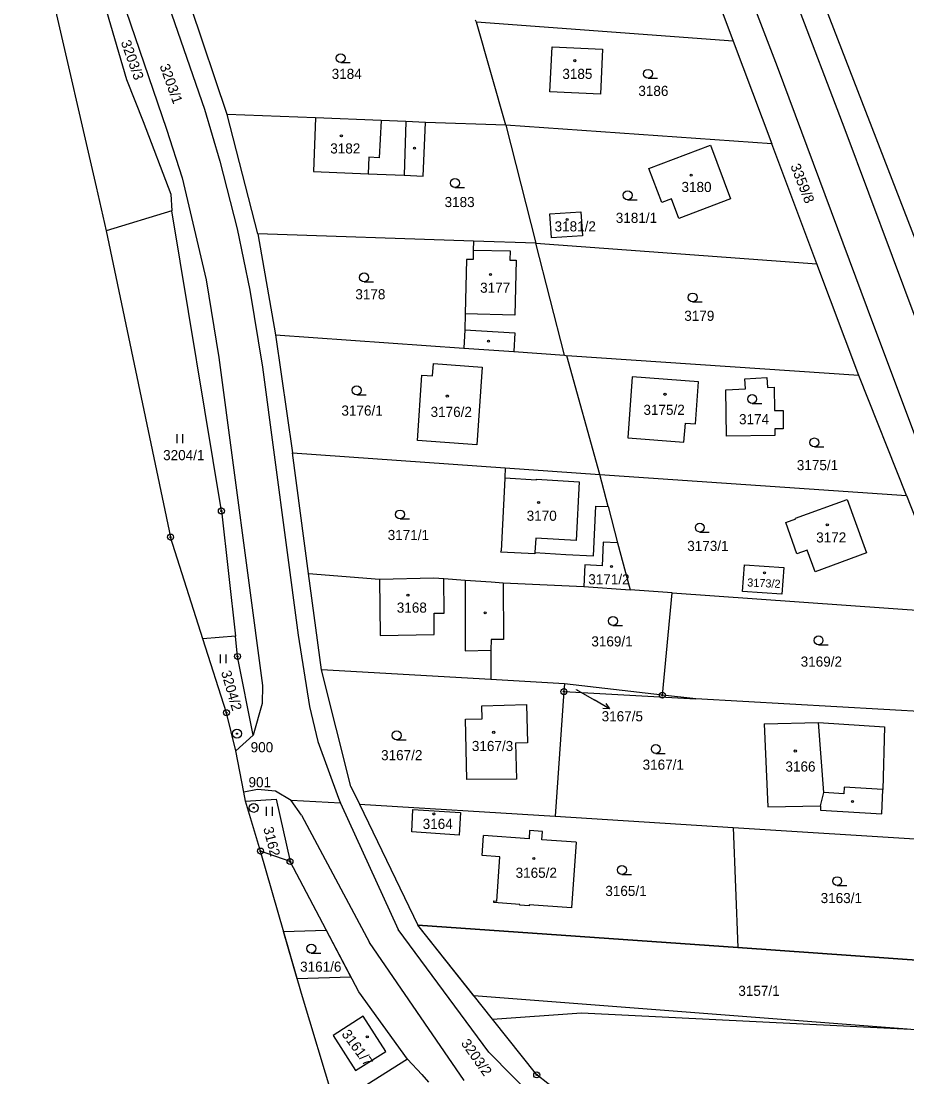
# Model space of a CAD drawing. Extents: x -755819 to -753140, y -1169796 to -1166000.
# Drawn here: x -754247.6 to -754098.6, y -1169675.5 to -1169498 of the extents above; entities that cross this region are included whole.
import ezdxf

# ---------------------------------------------------------------- set-up
doc = ezdxf.new("R2010")
doc.units = 0
for name, color, linetype in [('Vrstva 1', 7, 'Continuous'), ('Vrstva 13', 7, 'Continuous'), ('Vrstva 16', 7, 'Continuous'), ('Vrstva 17', 7, 'Continuous'), ('Vrstva 18', 7, 'Continuous'), ('Vrstva 19', 7, 'Continuous'), ('Vrstva 24', 7, 'Continuous'), ('Vrstva 25', 7, 'Continuous'), ('Vrstva 27', 7, 'Continuous'), ('Vrstva 4', 7, 'Continuous'), ('Vrstva 6', 7, 'Continuous')]:
    doc.layers.add(name, color=color, linetype=linetype)

msp = doc.modelspace()

# ---------------------------------------------------------------- linework, layer by layer
at = {"layer": 'Vrstva 1'}
for p, q in [((-754124.54, -1169463.98), (-754097.09, -1169534.95)), ((-754120.39, -1169505.66), (-754134.47, -1169468.92)), ((-754134.3, -1169483.93), (-754127.84, -1169501.33)), ((-754232.95, -1169487.36), (-754223.15, -1169516.12)), ((-754225.64, -1169486.93), (-754216.78, -1169512.79)), ((-754235.36, -1169489.1), (-754229.85, -1169507.79)), ((-754212.93, -1169513.65), (-754219.05, -1169495.48)), ((-754171, -1169498.11), (-754171.18, -1169497.81)), ((-754127.84, -1169501.33), (-754171, -1169498.11)), ((-754166.07, -1169515.47), (-754171, -1169498.11)), ((-754158.67, -1169509.85), (-754158.28, -1169502.3)), ((-754158.28, -1169502.3), (-754149.8, -1169502.7)), ((-754149.8, -1169502.7), (-754150.13, -1169510.23)), ((-754127.84, -1169501.33), (-754121.34, -1169518.58)), ((-754105.23, -1169546.26), (-754120.39, -1169505.66)), ((-754229.85, -1169507.79), (-754227.05, -1169514.85)), ((-754150.13, -1169510.23), (-754158.67, -1169509.85)), ((-754216.78, -1169512.79), (-754214.15, -1169521.5)), ((-754227.05, -1169514.85), (-754222.4, -1169527.04)), ((-754198.07, -1169514.21), (-754212.93, -1169513.65)), ((-754207.77, -1169533.74), (-754212.93, -1169513.65)), ((-754198.07, -1169514.21), (-754198.44, -1169523.24)), ((-754187.05, -1169514.68), (-754198.07, -1169514.21)), ((-754182.9, -1169514.85), (-754187.05, -1169514.68)), ((-754179.58, -1169514.99), (-754182.9, -1169514.85)), ((-754179.95, -1169524.02), (-754179.58, -1169514.99)), ((-754166.07, -1169515.47), (-754179.58, -1169514.99)), ((-754223.15, -1169516.12), (-754220.49, -1169524.34)), ((-754121.34, -1169518.58), (-754166.07, -1169515.47)), ((-754166.07, -1169515.47), (-754161.04, -1169535.31)), ((-754142.01, -1169522.75), (-754131.63, -1169518.81)), ((-754131.63, -1169518.81), (-754128.27, -1169527.84)), ((-754113.75, -1169538.75), (-754121.34, -1169518.58)), ((-754214.15, -1169521.5), (-754211.27, -1169532.88)), ((-754198.44, -1169523.24), (-754189.25, -1169523.64)), ((-754189.25, -1169523.64), (-754183.17, -1169523.88)), ((-754183.17, -1169523.88), (-754179.95, -1169524.02)), ((-754139.84, -1169528.48), (-754142.01, -1169522.75)), ((-754220.49, -1169524.34), (-754216.47, -1169541.49)), ((-754222.4, -1169527.04), (-754222.27, -1169529.89)), ((-754138.21, -1169527.87), (-754139.84, -1169528.48)), ((-754136.97, -1169531.14), (-754138.21, -1169527.87)), ((-754128.27, -1169527.84), (-754136.97, -1169531.14)), ((-754222.27, -1169529.89), (-754233.29, -1169533.21)), ((-754213.91, -1169580.33), (-754222.27, -1169529.89)), ((-754158.68, -1169530.39), (-754153.45, -1169530.02)), ((-754158.38, -1169534.43), (-754158.68, -1169530.39)), ((-754153.45, -1169530.02), (-754153.15, -1169534.08)), ((-754211.27, -1169532.88), (-754209.11, -1169543.21)), ((-754171.52, -1169534.96), (-754207.77, -1169533.74)), ((-754207.77, -1169533.74), (-754204.81, -1169550.71)), ((-754153.15, -1169534.08), (-754158.38, -1169534.43)), ((-754171.55, -1169536.46), (-754171.58, -1169538.05)), ((-754171.52, -1169534.96), (-754171.55, -1169536.46)), ((-754161.04, -1169535.31), (-754171.52, -1169534.96)), ((-754156.18, -1169554.11), (-754161.04, -1169535.31)), ((-754161.04, -1169535.31), (-754113.75, -1169538.75)), ((-754172.68, -1169538.03), (-754172.92, -1169547.18)), ((-754171.58, -1169538.05), (-754172.68, -1169538.03)), ((-754106.67, -1169557.57), (-754113.75, -1169538.75)), ((-754216.47, -1169541.49), (-754214.32, -1169554.53)), ((-754209.11, -1169543.21), (-754206.99, -1169556.16)), ((-754172.92, -1169547.18), (-754172.97, -1169549.88)), ((-754090.22, -1169586.43), (-754105.23, -1169546.26)), ((-754204.81, -1169550.71), (-754173.12, -1169552.98)), ((-754204.81, -1169550.71), (-754201.96, -1169570.53)), ((-754172.97, -1169549.88), (-754173.12, -1169552.98)), ((-754173.12, -1169552.98), (-754164.74, -1169553.49)), ((-754164.74, -1169553.49), (-754156.18, -1169554.11)), ((-754156.18, -1169554.11), (-754155.78, -1169554.22)), ((-754150.26, -1169574.2), (-754155.78, -1169554.22)), ((-754106.67, -1169557.57), (-754155.78, -1169554.22)), ((-754214.32, -1169554.53), (-754206.99, -1169609.66)), ((-754178.39, -1169557.63), (-754178.24, -1169555.53)), ((-754178.24, -1169555.53), (-754170.05, -1169556.15)), ((-754170.05, -1169556.15), (-754170.96, -1169569.19)), ((-754206.99, -1169556.16), (-754200.97, -1169601.19)), ((-754180.94, -1169568.49), (-754180.18, -1169557.5)), ((-754180.18, -1169557.5), (-754178.39, -1169557.63)), ((-754144.82, -1169557.79), (-754145.57, -1169568.06)), ((-754133.67, -1169558.6), (-754144.82, -1169557.79)), ((-754125.86, -1169558.1), (-754122.15, -1169557.87)), ((-754122.15, -1169557.87), (-754122.05, -1169559.59)), ((-754098.65, -1169577.71), (-754106.67, -1169557.57)), ((-754134.16, -1169565.68), (-754133.67, -1169558.6)), ((-754125.76, -1169559.82), (-754125.86, -1169558.1)), ((-754122.05, -1169559.59), (-754120.91, -1169559.54)), ((-754120.91, -1169559.54), (-754120.87, -1169563.43)), ((-754129.06, -1169559.94), (-754125.76, -1169559.82)), ((-754128.94, -1169567.73), (-754129.06, -1169559.94)), ((-754120.87, -1169563.43), (-754119.42, -1169563.42)), ((-754119.42, -1169563.42), (-754119.4, -1169566.53)), ((-754136.11, -1169568.75), (-754135.86, -1169565.59)), ((-754135.86, -1169565.59), (-754134.16, -1169565.68)), ((-754119.4, -1169566.53), (-754120.84, -1169566.54)), ((-754120.84, -1169566.54), (-754120.83, -1169567.65)), ((-754170.96, -1169569.19), (-754180.94, -1169568.49)), ((-754145.57, -1169568.06), (-754136.11, -1169568.75)), ((-754120.83, -1169567.65), (-754128.94, -1169567.73)), ((-754201.96, -1169570.53), (-754166.15, -1169573.07)), ((-754199.27, -1169590.84), (-754201.96, -1169570.53)), ((-754166.15, -1169573.07), (-754166.23, -1169574.76)), ((-754166.15, -1169573.07), (-754150.26, -1169574.2)), ((-754166.24, -1169574.87), (-754166.87, -1169587.05)), ((-754166.23, -1169574.76), (-754166.24, -1169574.87)), ((-754148.88, -1169579.57), (-754150.26, -1169574.2)), ((-754150.26, -1169574.2), (-754098.65, -1169577.71)), ((-754117.33, -1169581.52), (-754108.65, -1169578.39)), ((-754108.65, -1169578.39), (-754105.85, -1169586.16)), ((-754098.65, -1169577.71), (-754090.97, -1169597.45)), ((-754213.91, -1169580.33), (-754211.56, -1169601.41)), ((-754151.32, -1169587.88), (-754150.93, -1169579.51)), ((-754150.93, -1169579.51), (-754148.88, -1169579.57)), ((-754148.88, -1169579.57), (-754147.3, -1169585.69)), ((-754118.98, -1169582.28), (-754117.28, -1169581.66)), ((-754117.12, -1169587.54), (-754118.98, -1169582.28)), ((-754117.28, -1169581.66), (-754117.33, -1169581.52)), ((-754149.7, -1169585.59), (-754149.86, -1169589.53)), ((-754147.3, -1169585.69), (-754149.7, -1169585.59)), ((-754147.3, -1169585.69), (-754145.18, -1169593.58)), ((-754105.85, -1169586.16), (-754105.41, -1169587.38)), ((-754166.88, -1169587.24), (-754166.87, -1169587.05)), ((-754161.19, -1169587.53), (-754166.88, -1169587.24)), ((-754161.18, -1169587.34), (-754161.19, -1169587.53)), ((-754161.18, -1169587.34), (-754155.98, -1169587.63)), ((-754155.98, -1169587.63), (-754151.32, -1169587.88)), ((-754115.38, -1169586.91), (-754117.12, -1169587.54)), ((-754114.06, -1169590.58), (-754115.38, -1169586.91)), ((-754105.41, -1169587.38), (-754114.06, -1169590.58)), ((-754152.8, -1169589.41), (-754152.94, -1169593.01)), ((-754149.86, -1169589.53), (-754152.8, -1169589.41)), ((-754126.24, -1169593.87), (-754125.92, -1169589.4)), ((-754125.92, -1169589.4), (-754119.32, -1169589.81)), ((-754119.32, -1169589.81), (-754119.64, -1169594.33)), ((-754199.27, -1169590.84), (-754187.29, -1169591.8)), ((-754197.05, -1169607.04), (-754199.27, -1169590.84)), ((-754187.29, -1169591.8), (-754178.18, -1169591.58)), ((-754178.18, -1169591.58), (-754176.48, -1169591.7)), ((-754176.48, -1169591.7), (-754172.91, -1169591.96)), ((-754172.91, -1169591.96), (-754168.55, -1169592.26)), ((-754168.55, -1169592.26), (-754166.54, -1169592.41)), ((-754166.54, -1169592.41), (-754152.94, -1169593.01)), ((-754166.54, -1169592.41), (-754166.44, -1169601.94)), ((-754152.94, -1169593.01), (-754145.18, -1169593.58)), ((-754138.1, -1169594.09), (-754145.18, -1169593.58)), ((-754139.73, -1169611.3), (-754138.1, -1169594.09)), ((-754138.1, -1169594.09), (-754090.97, -1169597.45)), ((-754119.64, -1169594.33), (-754126.24, -1169593.87)), ((-754211.19, -1169604.79), (-754211.56, -1169601.41)), ((-754200.97, -1169601.19), (-754199.08, -1169613.21)), ((-754168.54, -1169601.94), (-754168.57, -1169603.73)), ((-754166.44, -1169601.94), (-754168.54, -1169601.94)), ((-754168.57, -1169603.73), (-754168.58, -1169608.67)), ((-754208.58, -1169618.01), (-754211.19, -1169604.79)), ((-754168.58, -1169608.67), (-754197.05, -1169607.04)), ((-754192.11, -1169626.67), (-754197.05, -1169607.04)), ((-754156.21, -1169609.38), (-754168.58, -1169608.67)), ((-754156.21, -1169609.38), (-754156.3, -1169610.71)), ((-754139.73, -1169611.3), (-754156.21, -1169609.38)), ((-754206.99, -1169609.66), (-754207.08, -1169612.68)), ((-754156.3, -1169610.71), (-754157.74, -1169631.68)), ((-754156.3, -1169610.71), (-754134.11, -1169611.95)), ((-754207.08, -1169612.68), (-754208.58, -1169618.01)), ((-754170.09, -1169613.12), (-754162.58, -1169612.86)), ((-754162.58, -1169612.86), (-754162.41, -1169619.34)), ((-754134.11, -1169611.95), (-754139.73, -1169611.3)), ((-754084.37, -1169614.72), (-754134.11, -1169611.95)), ((-754199.08, -1169613.21), (-754197.67, -1169619.08)), ((-754170.02, -1169615.28), (-754170.09, -1169613.12)), ((-754172.87, -1169615.35), (-754170.02, -1169615.28)), ((-754172.6, -1169625.47), (-754172.87, -1169615.35)), ((-754122.6, -1169616.12), (-754113.47, -1169615.89)), ((-754122.6, -1169616.12), (-754122.02, -1169630.08)), ((-754113.47, -1169615.89), (-754102.38, -1169616.61)), ((-754211.46, -1169620.66), (-754208.58, -1169618.01)), ((-754102.38, -1169616.61), (-754102.66, -1169627.16)), ((-754197.67, -1169619.08), (-754194.22, -1169628.64)), ((-754162.41, -1169619.34), (-754164.44, -1169619.39)), ((-754164.44, -1169619.39), (-754164.27, -1169625.43)), ((-754207.81, -1169627.17), (-754210.12, -1169627.6)), ((-754204.81, -1169627.47), (-754207.81, -1169627.17)), ((-754192.11, -1169626.67), (-754190.67, -1169629.63)), ((-754164.27, -1169625.43), (-754172.6, -1169625.47)), ((-754102.8, -1169631.24), (-754102.66, -1169627.16)), ((-754209.83, -1169629.12), (-754204.7, -1169628.78)), ((-754202.17, -1169628.99), (-754204.81, -1169627.47)), ((-754204.7, -1169628.78), (-754202.37, -1169639.27)), ((-754194.22, -1169628.64), (-754193.85, -1169629.45)), ((-754193.85, -1169629.45), (-754202.17, -1169628.99)), ((-754190.67, -1169629.63), (-754157.74, -1169631.68)), ((-754190.67, -1169629.63), (-754180.86, -1169650)), ((-754181.9, -1169634.28), (-754181.71, -1169630.53)), ((-754181.71, -1169630.53), (-754173.69, -1169631.02)), ((-754122.02, -1169630.08), (-754113.14, -1169629.9)), ((-754113.14, -1169629.9), (-754113.12, -1169630.66)), ((-754113.12, -1169630.66), (-754102.8, -1169631.24)), ((-754173.69, -1169631.02), (-754173.89, -1169634.82)), ((-754157.74, -1169631.68), (-754127.84, -1169633.54)), ((-754162.06, -1169634.05), (-754162.16, -1169635.45)), ((-754159.9, -1169634.21), (-754162.06, -1169634.05)), ((-754160, -1169635.61), (-754159.9, -1169634.21)), ((-754127.84, -1169633.54), (-754127.03, -1169653.74)), ((-754127.84, -1169633.54), (-754076.24, -1169636.76)), ((-754173.89, -1169634.82), (-754181.9, -1169634.28)), ((-754170.04, -1169638.27), (-754169.82, -1169634.89)), ((-754162.16, -1169635.45), (-754169.82, -1169634.89)), ((-754154.24, -1169636.03), (-754160, -1169635.61)), ((-754154.24, -1169636.03), (-754155.04, -1169647.08)), ((-754202.37, -1169639.27), (-754207.32, -1169637.52)), ((-754190.8, -1169661.2), (-754202.37, -1169639.27)), ((-754167.07, -1169638.47), (-754170.04, -1169638.27)), ((-754167.59, -1169645.93), (-754167.07, -1169638.47)), ((-754168.11, -1169646.18), (-754168.09, -1169645.89)), ((-754163.69, -1169646.49), (-754168.11, -1169646.18)), ((-754168.09, -1169645.89), (-754167.59, -1169645.93)), ((-754163.7, -1169646.61), (-754163.69, -1169646.49)), ((-754162.15, -1169646.72), (-754163.7, -1169646.61)), ((-754162.14, -1169646.58), (-754162.15, -1169646.72)), ((-754155.04, -1169647.08), (-754162.14, -1169646.58)), ((-754127.03, -1169653.74), (-754180.86, -1169650)), ((-754168.32, -1169665.78), (-754180.86, -1169650)), ((-754070.63, -1169657.73), (-754127.03, -1169653.74)), ((-754182.6, -1169672.49), (-754190.8, -1169661.2)), ((-754190.05, -1169665.3), (-754195.13, -1169668.55)), ((-754186.26, -1169671.22), (-754190.05, -1169665.3)), ((-754160.87, -1169675.16), (-754168.32, -1169665.78)), ((-754195.13, -1169668.55), (-754191.34, -1169674.4)), ((-754191.34, -1169674.4), (-754186.26, -1169671.22)), ((-754182.6, -1169672.49), (-754194.8, -1169680.19)), ((-754182.6, -1169672.49), (-754180.22, -1169675.11)), ((-754180.22, -1169675.11), (-754179.08, -1169676.38)), ((-754120.55, -1169706.56), (-754160.87, -1169675.16))]:
    msp.add_line(p, q, dxfattribs=at)
at = {"layer": 'Vrstva 13'}
for p, q in [((-754247.6, -1169471.19), (-754234.99, -1169525.84)), ((-754234.99, -1169525.84), (-754233.29, -1169533.21)), ((-754233.29, -1169533.21), (-754222.46, -1169584.72)), ((-754217.01, -1169601.86), (-754222.46, -1169584.72)), ((-754213.06, -1169614.25), (-754217.01, -1169601.86)), ((-754211.46, -1169620.66), (-754213.06, -1169614.25)), ((-754210.12, -1169627.6), (-754211.46, -1169620.66)), ((-754209.83, -1169629.12), (-754210.12, -1169627.6)), ((-754207.32, -1169637.52), (-754209.83, -1169629.12)), ((-754200.46, -1169661.48), (-754207.32, -1169637.52)), ((-754194.8, -1169680.19), (-754200.46, -1169661.48))]:
    msp.add_line(p, q, dxfattribs=at)
at = {"layer": 'Vrstva 16'}
for p in [(-754154.23, -1169610.35), (-754148.63, -1169613.63)]:
    msp.add_line(p, (-754151.22, -1169612.11), dxfattribs=at)
msp.add_lwpolyline([(-754149.24, -1169612.69), (-754148.63, -1169613.63), (-754149.75, -1169613.55)], dxfattribs=at)
at = {"layer": 'Vrstva 24'}
for centre, radius in [((-754213.91, -1169580.33), 0.5), ((-754213.91, -1169580.33), 0.1), ((-754222.46, -1169584.72), 0.5), ((-754222.46, -1169584.72), 0.1), ((-754211.19, -1169604.79), 0.5), ((-754211.19, -1169604.79), 0.1), ((-754156.3, -1169610.71), 0.5), ((-754156.3, -1169610.71), 0.1), ((-754139.73, -1169611.3), 0.5), ((-754139.73, -1169611.3), 0.1), ((-754213.06, -1169614.25), 0.5), ((-754213.06, -1169614.25), 0.1), ((-754211.29, -1169617.77), 0.75), ((-754211.29, -1169617.77), 0.1), ((-754208.47, -1169630.26), 0.75), ((-754208.47, -1169630.26), 0.1), ((-754207.32, -1169637.52), 0.5), ((-754207.32, -1169637.52), 0.1), ((-754202.37, -1169639.27), 0.5), ((-754202.37, -1169639.27), 0.1), ((-754160.87, -1169675.16), 0.5), ((-754160.87, -1169675.16), 0.1)]:
    msp.add_circle(centre, radius, dxfattribs=at)
at = {"layer": 'Vrstva 25'}
for p, q in [((-754193.84, -1169504.94), (-754192.24, -1169504.94)), ((-754142.15, -1169507.57), (-754140.55, -1169507.57)), ((-754174.62, -1169525.94), (-754173.02, -1169525.94)), ((-754145.58, -1169528), (-754143.98, -1169528)), ((-754189.91, -1169541.81), (-754188.31, -1169541.81)), ((-754134.65, -1169545.18), (-754133.05, -1169545.18)), ((-754191.15, -1169560.79), (-754189.55, -1169560.79)), ((-754124.63, -1169562.26), (-754123.03, -1169562.26)), ((-754221.37, -1169568.93), (-754221.37, -1169567.43)), ((-754220.37, -1169568.93), (-754220.37, -1169567.43)), ((-754114.17, -1169569.56), (-754112.57, -1169569.56)), ((-754183.86, -1169581.67), (-754182.26, -1169581.67)), ((-754133.44, -1169583.87), (-754131.84, -1169583.87)), ((-754148.04, -1169599.58), (-754146.44, -1169599.58)), ((-754113.47, -1169602.84), (-754111.87, -1169602.84)), ((-754214.08, -1169605.95), (-754214.08, -1169604.45)), ((-754213.08, -1169605.95), (-754213.08, -1169604.45)), ((-754184.43, -1169618.81), (-754182.83, -1169618.81)), ((-754140.84, -1169621.11), (-754139.24, -1169621.11)), ((-754206.3, -1169631.57), (-754206.3, -1169630.07)), ((-754205.3, -1169631.57), (-754205.3, -1169630.07)), ((-754146.54, -1169641.45), (-754144.94, -1169641.45)), ((-754110.33, -1169643.33), (-754108.73, -1169643.33)), ((-754198.79, -1169654.67), (-754197.19, -1169654.67))]:
    msp.add_line(p, q, dxfattribs=at)
for centre, radius in [((-754193.84, -1169504.19), 0.75), ((-754154.46, -1169504.61), 0.175), ((-754142.15, -1169506.82), 0.75), ((-754193.73, -1169517.25), 0.175), ((-754181.42, -1169519.34), 0.175), ((-754134.88, -1169523.85), 0.175), ((-754174.62, -1169525.19), 0.75), ((-754145.58, -1169527.25), 0.75), ((-754155.75, -1169531.31), 0.175), ((-754189.91, -1169541.06), 0.75), ((-754168.64, -1169540.56), 0.175), ((-754134.65, -1169544.43), 0.75), ((-754168.99, -1169551.77), 0.175), ((-754191.15, -1169560.04), 0.75), ((-754175.91, -1169561.01), 0.175), ((-754139.29, -1169560.71), 0.175), ((-754124.63, -1169561.51), 0.75), ((-754114.17, -1169568.81), 0.75), ((-754160.55, -1169578.91), 0.175), ((-754183.86, -1169580.92), 0.75), ((-754133.44, -1169583.12), 0.75), ((-754111.99, -1169582.66), 0.175), ((-754148.3, -1169589.67), 0.175), ((-754122.55, -1169590.74), 0.175), ((-754182.53, -1169594.49), 0.175), ((-754169.53, -1169597.47), 0.175), ((-754148.04, -1169598.83), 0.75), ((-754113.47, -1169602.09), 0.75), ((-754184.43, -1169618.06), 0.75), ((-754168.11, -1169617.55), 0.175), ((-754140.84, -1169620.36), 0.75), ((-754117.37, -1169620.7), 0.175), ((-754107.76, -1169629.19), 0.175), ((-754178.17, -1169631.28), 0.175), ((-754161.37, -1169638.78), 0.175), ((-754146.54, -1169640.7), 0.75), ((-754110.33, -1169642.58), 0.75), ((-754198.79, -1169653.92), 0.75), ((-754189.37, -1169668.77), 0.175)]:
    msp.add_circle(centre, radius, dxfattribs=at)
at = {"layer": 'Vrstva 27'}
for p, q in [((-754171.44, -1169661.86), (-754180.86, -1169650)), ((-754180.86, -1169650), (-754127.03, -1169653.74)), ((-754203.44, -1169651.07), (-754196.27, -1169650.83)), ((-754201.17, -1169659), (-754203.44, -1169651.07)), ((-754196.27, -1169650.83), (-754192.12, -1169658.7)), ((-754127.03, -1169653.74), (-754070.63, -1169657.73)), ((-754192.12, -1169658.7), (-754201.17, -1169659)), ((-754098.56, -1169667.45), (-754171.44, -1169661.86))]:
    msp.add_line(p, q, dxfattribs=at)
at = {"layer": 'Vrstva 4'}
for p, q in [((-754120.25, -1169486.71), (-754109.02, -1169516.17)), ((-754187.05, -1169514.68), (-754187.38, -1169520.95)), ((-754182.9, -1169514.85), (-754183.17, -1169523.88)), ((-754109.02, -1169516.17), (-754097.09, -1169548.16)), ((-754189.1, -1169520.86), (-754189.25, -1169523.64)), ((-754187.38, -1169520.95), (-754189.1, -1169520.86)), ((-754171.55, -1169536.46), (-754165.36, -1169536.59)), ((-754165.36, -1169536.59), (-754165.39, -1169538.16)), ((-754165.39, -1169538.16), (-754164.35, -1169538.18)), ((-754164.35, -1169538.18), (-754164.56, -1169547.41)), ((-754164.56, -1169547.41), (-754172.92, -1169547.18)), ((-754172.97, -1169549.88), (-754164.55, -1169550.39)), ((-754164.55, -1169550.39), (-754164.74, -1169553.49)), ((-754166.23, -1169574.76), (-754160.89, -1169575.08)), ((-754160.89, -1169575.08), (-754160.89, -1169575)), ((-754160.89, -1169575), (-754153.74, -1169575.41)), ((-754153.74, -1169575.41), (-754154.25, -1169585.28)), ((-754161.03, -1169584.89), (-754161.18, -1169587.34)), ((-754154.25, -1169585.28), (-754161.03, -1169584.89)), ((-754187.29, -1169591.8), (-754187.22, -1169601.29)), ((-754176.45, -1169597.5), (-754176.48, -1169591.7)), ((-754172.91, -1169591.96), (-754172.89, -1169603.83)), ((-754178.13, -1169597.52), (-754176.45, -1169597.5)), ((-754178.1, -1169601.13), (-754178.13, -1169597.52)), ((-754187.22, -1169601.29), (-754178.1, -1169601.13)), ((-754172.89, -1169603.83), (-754168.57, -1169603.73)), ((-754112.58, -1169627.7), (-754113.47, -1169615.89)), ((-754109.15, -1169626.76), (-754109.22, -1169627.88)), ((-754102.66, -1169627.16), (-754109.15, -1169626.76)), ((-754113.14, -1169629.9), (-754112.58, -1169627.7)), ((-754109.22, -1169627.88), (-754112.58, -1169627.7)), ((-754200.43, -1169631.5), (-754202.17, -1169628.99)), ((-754193.85, -1169629.45), (-754184.19, -1169650.69)), ((-754200.43, -1169631.5), (-754189, -1169652.88)), ((-754168.9, -1169671.34), (-754184.19, -1169650.69)), ((-754173.1, -1169676.08), (-754189, -1169652.88)), ((-754168.9, -1169671.34), (-754158.95, -1169681.4))]:
    msp.add_line(p, q, dxfattribs=at)
at = {"layer": 'Vrstva 6'}
for p, q in [((-754211.56, -1169601.41), (-754217.01, -1169601.86)), ((-754168.32, -1169665.78), (-754153.32, -1169664.75)), ((-754153.32, -1169664.75), (-754067.61, -1169668.98))]:
    msp.add_line(p, q, dxfattribs=at)

# ---------------------------------------------------------------- texts
at = {"layer": 'Vrstva 16'}
msp.add_text('3167/5', height=1.7, dxfattribs=at).set_placement((-754149.95, -1169615.7))
at = {"layer": 'Vrstva 17'}
for s, p in [('900', (-754208.99, -1169620.91)), ('901', (-754209.35, -1169626.79))]:
    msp.add_text(s, height=1.7, dxfattribs=at).set_placement(p)
at = {"layer": 'Vrstva 18'}
for s, rotation, p in [('3203/3', 289.8021, (-754230.86, -1169501.49)), ('3203/1', 289.8021, (-754224.33, -1169505.5)), ('3359/8', 291.5782, (-754118.23, -1169522.32)), ('3204/2', 286.1924, (-754213.99, -1169607.42)), ('3162', 284.4162, (-754206.89, -1169633.67)), ('3203/2', 305.2719, (-754173.69, -1169669.85))]:
    msp.add_text(s, height=1.7, rotation=rotation, dxfattribs=at).set_placement(p)
for s, height, p in [('3184', 1.7, (-754195.36, -1169507.68)), ('3186', 1.7, (-754143.78, -1169510.54)), ('3183', 1.7, (-754176.37, -1169529.23)), ('3181/1', 1.7, (-754147.57, -1169531.89)), ('3178', 1.7, (-754191.38, -1169544.74)), ('3179', 1.7, (-754136.05, -1169548.36)), ('3176/1', 1.7, (-754193.72, -1169564.3)), ('3174', 1.7, (-754126.84, -1169565.75)), ('3204/1', 1.7, (-754223.71, -1169571.79)), ('3175/1', 1.7, (-754117.12, -1169573.47)), ('3171/1', 1.7, (-754185.94, -1169585.22)), ('3173/1', 1.7, (-754135.55, -1169587.06)), ('3169/1', 1.7, (-754151.68, -1169603.11)), ('3169/2', 1.7, (-754116.47, -1169606.51)), ('3167/5', 0.1, (-754154.46, -1169610.35)), ('3167/2', 1.7, (-754187.05, -1169622.24)), ('3167/1', 1.7, (-754143.06, -1169623.84)), ('3165/1', 1.7, (-754149.33, -1169645.07)), ('3163/1', 1.7, (-754113.11, -1169646.27)), ('3161/6', 1.7, (-754200.67, -1169657.81)), ('3157/1', 1.7, (-754126.96, -1169661.87))]:
    msp.add_text(s, height=height, dxfattribs=at).set_placement(p)
at = {"layer": 'Vrstva 19'}
for s, p in [('3185', (-754156.56, -1169507.68)), ('3182', (-754195.6, -1169520.22)), ('3180', (-754136.52, -1169526.7)), ('3181/2', (-754157.87, -1169533.32)), ('3177', (-754170.39, -1169543.64)), ('3176/2', (-754178.72, -1169564.52)), ('3175/2', (-754142.92, -1169564.17)), ('3170', (-754162.56, -1169581.98)), ('3172', (-754113.86, -1169585.63)), ('3171/2', (-754152.2, -1169592.67)), ('3168', (-754184.41, -1169597.43)), ('3167/3', (-754171.78, -1169620.7)), ('3166', (-754119.03, -1169624.15)), ('3164', (-754180.05, -1169633.8)), ('3165/2', (-754164.42, -1169642.02))]:
    msp.add_text(s, height=1.7, dxfattribs=at).set_placement(p)
for s, height, rotation, p in [('3173/2', 1.37, 357.2965, (-754125.49, -1169593.02)), ('3161/7', 1.7, 306.4751, (-754193.78, -1169668.32))]:
    msp.add_text(s, height=height, rotation=rotation, dxfattribs=at).set_placement(p)

doc.saveas('drawing.dxf')
